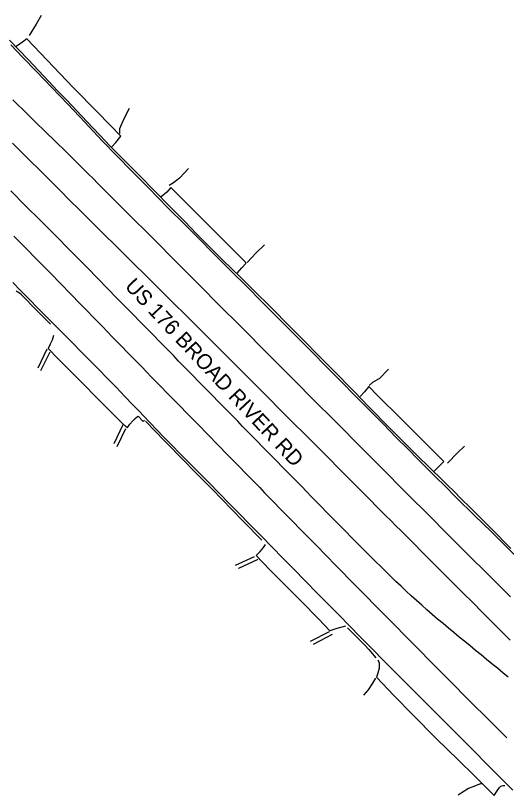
# Model space of a CAD drawing. Extents: x 1970211 to 1973046, y 801032 to 804001.
# Drawn here: x 1972080.5 to 1972255, y 802005.1 to 802282.3 of the extents above; entities that cross this region are included whole.
import ezdxf

# ---------------------------------------------------------------- set-up
doc = ezdxf.new("R2010")
doc.units = 0
for name, color, linetype in [('RD_EX_Conc', 7, 'Continuous'), ('RD_EX_Road', 7, 'Continuous'), ('RD_EX_Road_Paint', 7, 'Continuous'), ('RD_TX_RoadID', 7, 'Continuous')]:
    doc.layers.add(name, color=color, linetype=linetype)

msp = doc.modelspace()

# ---------------------------------------------------------------- linework, layer by layer
at = {"layer": 'RD_EX_Conc'}
for points in [[(1972078.39, 802273.57), (1972081.68, 802270.1), (1972084.94, 802266.67), (1972088.67, 802262.74), (1972092.37, 802258.83), (1972095.56, 802255.47), (1972098.68, 802252.21), (1972102.14, 802248.61), (1972106.01, 802244.56), (1972110.35, 802239.96), (1972114.14, 802235.95), (1972116.34, 802233.7), (1972117.89, 802232.16), (1972119.76, 802230.29), (1972121.47, 802228.58), (1972122.55, 802227.49), (1972123.82, 802226.22), (1972126.09, 802223.91), (1972128.4, 802221.55), (1972129.79, 802220.11), (1972131.3, 802218.56), (1972133.97, 802215.88), (1972137.29, 802212.53), (1972140.78, 802208.98), (1972144.77, 802204.91), (1972149.62, 802200), (1972154.24, 802195.38), (1972157.53, 802192.16), (1972160.33, 802189.46), (1972163.44, 802186.4), (1972166.67, 802183.19), (1972169.81, 802180.04), (1972172.99, 802176.84), (1972176.33, 802173.47), (1972179.87, 802169.91), (1972183.64, 802166.11), (1972187.6, 802162.13), (1972191.71, 802157.99), (1972195.51, 802154.16), (1972198.53, 802151.09), (1972201.09, 802148.46), (1972203.49, 802145.95), (1972205.89, 802143.45), (1972208.45, 802140.86), (1972211.35, 802137.93), (1972214.79, 802134.44), (1972218.3, 802130.89), (1972221.41, 802127.79), (1972224.22, 802125.03), (1972226.79, 802122.49), (1972229.05, 802120.28), (1972230.93, 802118.47), (1972232.58, 802116.88), (1972234.15, 802115.34), (1972236.14, 802113.36), (1972239.05, 802110.46), (1972242, 802107.53), (1972244.1, 802105.46), (1972246.16, 802103.42), (1972248.98, 802100.56), (1972251.92, 802097.58), (1972254.32, 802095.16), (1972256.6, 802092.88)], [(1972114.73, 802235.71), (1972116.12, 802237.25), (1972117.98, 802239.48), (1972109.75, 802247.84), (1972100.93, 802256.8), (1972091.73, 802266.51), (1972084.49, 802274.07), (1972082.97, 802272.87), (1972080.68, 802271.35)], [(1972141.95, 802228.02), (1972138.83, 802224.5), (1972136.67, 802222.89), (1972135.11, 802221.96)], [(1972159.23, 802190.81), (1972160.93, 802192.61), (1972162.42, 802194.2), (1972162.42, 802194.53), (1972155.61, 802201.28), (1972147.87, 802209.03), (1972140.09, 802216.86), (1972135.75, 802221.24), (1972134.27, 802219.51), (1972132.26, 802217.89)], [(1972169, 802200.87), (1972166.06, 802197.95), (1972162.86, 802194.59)], [(1972092.99, 802172.59), (1972086.67, 802178.96), (1972084.09, 802181.6), (1972083.14, 802182.61), (1972082.52, 802183.12), (1972081.86, 802183.63), (1972080.68, 802184.37)], [(1972093.96, 802168.57), (1972093.49, 802166.97), (1972092.85, 802165.51), (1972092.14, 802163.93), (1972095.48, 802160.4), (1972103.46, 802152.51), (1972110.42, 802145.35), (1972118.51, 802137.32), (1972119.62, 802136.35), (1972120.25, 802135.87), (1972121.16, 802137.05), (1972122.19, 802138.24), (1972123.06, 802139.1), (1972123.8, 802139.79), (1972124.08, 802139.99), (1972125.93, 802138.07), (1972126.33, 802138.56)], [(1972088.49, 802157.1), (1972091.77, 802163.92)], [(1972213.03, 802156.67), (1972209.93, 802153.31), (1972207.43, 802151.86), (1972206.19, 802150.85)], [(1972229.31, 802120.34), (1972231.21, 802122.28), (1972232.76, 802123.83), (1972225.24, 802131.24), (1972217.53, 802139.02), (1972209.19, 802147.31), (1972206.11, 802150.45), (1972204.55, 802148.54), (1972202.99, 802146.9)], [(1972116.64, 802129.19), (1972119.66, 802135.6)], [(1972126.75, 802138.15), (1972130.28, 802134.5), (1972133.23, 802131.45), (1972135.8, 802128.8), (1972138.25, 802126.29), (1972140.79, 802123.71), (1972143.58, 802120.87), (1972146.73, 802117.65), (1972150.38, 802113.96), (1972154.05, 802110.23), (1972157.27, 802106.92), (1972161.47, 802102.59), (1972168.03, 802095.8)], [(1972240.08, 802129.28), (1972237.66, 802126.85), (1972234.08, 802123.24)], [(1972197.82, 802065.23), (1972194.76, 802064.5), (1972192.24, 802063.68), (1972188.31, 802067.8), (1972181.94, 802074.32), (1972176.69, 802079.53), (1972170.9, 802085.31), (1972166.07, 802090.39), (1972167.46, 802091.79), (1972168.66, 802093.26), (1972169.35, 802094.35)], [(1972158.73, 802086.95), (1972165.44, 802090.06)], [(1972209.24, 802053.36), (1972209.75, 802052.22), (1972209.79, 802050.31), (1972209.34, 802048.54), (1972208.77, 802047.19), (1972215.03, 802040.64), (1972221.71, 802033.8), (1972230.04, 802025.31), (1972237.94, 802017.65), (1972243.51, 802012.16), (1972246.5, 802009.27), (1972250.67, 802005.14), (1972251.53, 802006.41), (1972252.49, 802007.95), (1972253.04, 802008.39), (1972253.88, 802008.62), (1972254.42, 802008.62)]]:
    msp.add_lwpolyline(points, dxfattribs=at)
at = {"layer": 'RD_EX_Road'}
for points in [[(1972089.59, 802282.31), (1972087.83, 802279.31), (1972085.34, 802275.23)], [(1972259.9, 802088.59), (1972254.78, 802093.69), (1972249.66, 802098.77), (1972243.69, 802104.66), (1972237.18, 802111.08), (1972232.7, 802115.49), (1972230.26, 802117.9), (1972227.41, 802120.76), (1972223.81, 802124.39), (1972219.91, 802128.34), (1972215.75, 802132.52), (1972211.26, 802137.08), (1972206.43, 802141.99), (1972201.4, 802147.09), (1972196.21, 802152.3), (1972191.1, 802157.47), (1972185.96, 802162.65), (1972180.15, 802168.51), (1972173.74, 802174.94), (1972167.95, 802180.73), (1972162.79, 802185.87), (1972157.15, 802191.52), (1972151.02, 802197.67), (1972145.55, 802203.16), (1972140.64, 802208.06), (1972134.69, 802214.04), (1972127.74, 802221.05), (1972121.72, 802227.14), (1972116.7, 802232.24), (1972111.23, 802237.96), (1972105.17, 802244.41), (1972099.16, 802250.75), (1972093.34, 802256.82), (1972087.93, 802262.44), (1972083.01, 802267.54), (1972078.79, 802271.9)], [(1972117.53, 802240.39), (1972117.62, 802242.22), (1972119.14, 802245.74), (1972121.02, 802249.43)], [(1972257.32, 802006.96), (1972253.8, 802010.49), (1972250.64, 802013.66), (1972247.69, 802016.64), (1972243.64, 802020.69), (1972238.54, 802025.8), (1972233.81, 802030.53), (1972229.62, 802034.74), (1972225.41, 802038.98), (1972221.05, 802043.36), (1972216.46, 802047.97), (1972211.71, 802052.78), (1972207.22, 802057.3), (1972203.05, 802061.48), (1972199.17, 802065.41), (1972195.5, 802069.15), (1972191.7, 802073.02), (1972187.72, 802077.07), (1972183.57, 802081.29), (1972179.31, 802085.61), (1972175.38, 802089.62), (1972171.74, 802093.34), (1972167.9, 802097.26), (1972163.85, 802101.38), (1972160, 802105.28), (1972156.41, 802108.93), (1972152.85, 802112.55), (1972149.3, 802116.18), (1972145.8, 802119.74), (1972142.37, 802123.2), (1972139.07, 802126.53), (1972136.05, 802129.59), (1972134.04, 802131.65), (1972132.89, 802132.85), (1972130.96, 802134.87), (1972128.21, 802137.73), (1972126.01, 802140.02), (1972124.4, 802141.71), (1972122.21, 802143.98), (1972119.33, 802146.97), (1972116.26, 802150.18), (1972113.13, 802153.47), (1972110.17, 802156.47), (1972107.36, 802159.24), (1972104.12, 802162.51), (1972100.53, 802166.22), (1972097.48, 802169.33), (1972094.96, 802171.86), (1972092.01, 802174.81), (1972088.58, 802178.25), (1972085.31, 802181.54), (1972082.31, 802184.58), (1972079.52, 802187.42)], [(1972089.46, 802156.14), (1972092.78, 802162.77)], [(1972115.6, 802130.23), (1972118.73, 802136.96)], [(1972159.8, 802085.86), (1972159.92, 802085.92), (1972166.7, 802089.12)], [(1972198.54, 802064.7), (1972202.25, 802060.95), (1972204.38, 802058.82), (1972206.13, 802056.94), (1972208.6, 802054.08)], [(1972185.3, 802059.99), (1972192.06, 802063.36)], [(1972186.38, 802058.9), (1972186.38, 802058.9), (1972193.19, 802062.39)], [(1972204.26, 802040.75), (1972205.92, 802042.7), (1972207.5, 802045), (1972208.62, 802046.78)], [(1972246.38, 802009.24), (1972245.8, 802009.21), (1972244.88, 802008.93), (1972243.99, 802008.56), (1972241.52, 802007.56), (1972239.22, 802006.17), (1972237.85, 802005.26)]]:
    msp.add_lwpolyline(points, dxfattribs=at)
at = {"layer": 'RD_EX_Road_Paint'}
for points in [[(1972256.4, 802075.73), (1972254.63, 802077.49), (1972252.86, 802079.26), (1972251.09, 802081.03), (1972249.32, 802082.79), (1972247.55, 802084.56), (1972245.78, 802086.32), (1972244.01, 802088.09), (1972242.24, 802089.85), (1972240.47, 802091.62), (1972238.7, 802093.38), (1972236.93, 802095.15), (1972235.16, 802096.92), (1972233.39, 802098.68), (1972231.63, 802100.45), (1972229.86, 802102.22), (1972228.1, 802103.99), (1972226.33, 802105.76), (1972224.57, 802107.53), (1972222.8, 802109.3), (1972221.04, 802111.08), (1972219.27, 802112.85), (1972217.51, 802114.62), (1972215.74, 802116.39), (1972213.98, 802118.16), (1972212.22, 802119.93), (1972210.45, 802121.7), (1972208.69, 802123.47), (1972206.92, 802125.24), (1972205.16, 802127.01), (1972203.39, 802128.78), (1972201.63, 802130.56), (1972199.86, 802132.33), (1972198.1, 802134.1), (1972196.33, 802135.87), (1972194.57, 802137.64), (1972192.8, 802139.41), (1972191.04, 802141.18), (1972189.27, 802142.95), (1972187.51, 802144.72), (1972185.75, 802146.49), (1972183.98, 802148.26), (1972182.22, 802150.03), (1972180.45, 802151.81), (1972178.69, 802153.58), (1972176.92, 802155.35), (1972175.16, 802157.12), (1972173.39, 802158.89), (1972171.63, 802160.66), (1972169.86, 802162.43), (1972168.1, 802164.2), (1972166.33, 802165.97), (1972164.57, 802167.74), (1972162.81, 802169.51), (1972161.04, 802171.28), (1972159.28, 802173.06), (1972157.51, 802174.83), (1972155.75, 802176.6), (1972153.98, 802178.37), (1972152.22, 802180.14), (1972150.45, 802181.91), (1972148.69, 802183.68), (1972146.92, 802185.45), (1972145.16, 802187.22), (1972143.39, 802188.99), (1972141.63, 802190.76), (1972139.86, 802192.54), (1972138.1, 802194.31), (1972136.34, 802196.08), (1972134.57, 802197.85), (1972132.81, 802199.62), (1972131.04, 802201.39), (1972129.28, 802203.16), (1972127.51, 802204.93), (1972125.75, 802206.7), (1972123.98, 802208.47), (1972122.22, 802210.24), (1972120.45, 802212.01), (1972118.69, 802213.78), (1972116.91, 802215.54), (1972115.14, 802217.31), (1972113.36, 802219.07), (1972111.59, 802220.83), (1972109.81, 802222.59), (1972108.04, 802224.35), (1972106.27, 802226.11), (1972104.49, 802227.87), (1972102.72, 802229.63), (1972100.94, 802231.39), (1972099.17, 802233.15), (1972097.39, 802234.91), (1972095.62, 802236.67), (1972093.84, 802238.43), (1972092.04, 802240.17), (1972090.25, 802241.91), (1972088.46, 802243.65), (1972086.66, 802245.39), (1972084.87, 802247.14), (1972083.08, 802248.88), (1972081.28, 802250.62), (1972079.49, 802252.36)], [(1972256.35, 802060.35), (1972254.58, 802062.11), (1972252.81, 802063.88), (1972251.04, 802065.65), (1972249.27, 802067.41), (1972247.5, 802069.18), (1972245.73, 802070.95), (1972243.96, 802072.71), (1972242.19, 802074.48), (1972240.42, 802076.24), (1972238.66, 802078.01), (1972236.89, 802079.78), (1972235.12, 802081.55), (1972233.35, 802083.32), (1972231.58, 802085.08), (1972229.82, 802086.85), (1972228.05, 802088.62), (1972226.28, 802090.39), (1972224.51, 802092.15), (1972222.75, 802093.93), (1972220.99, 802095.7), (1972219.22, 802097.47), (1972217.46, 802099.24), (1972215.7, 802101.01), (1972213.93, 802102.79), (1972212.17, 802104.56), (1972210.41, 802106.33), (1972208.64, 802108.1), (1972206.88, 802109.88), (1972205.12, 802111.65), (1972203.35, 802113.42), (1972201.59, 802115.19), (1972199.83, 802116.96), (1972198.06, 802118.74), (1972196.3, 802120.51), (1972194.54, 802122.28), (1972192.77, 802124.05), (1972191.01, 802125.82), (1972189.24, 802127.59), (1972187.47, 802129.36), (1972185.7, 802131.13), (1972183.93, 802132.89), (1972182.16, 802134.66), (1972180.39, 802136.42), (1972178.62, 802138.19), (1972176.86, 802139.96), (1972175.09, 802141.73), (1972173.33, 802143.5), (1972171.56, 802145.27), (1972169.8, 802147.04), (1972168.03, 802148.81), (1972166.27, 802150.58), (1972164.51, 802152.35), (1972162.74, 802154.13), (1972160.98, 802155.9), (1972159.21, 802157.67), (1972157.44, 802159.43), (1972155.67, 802161.2), (1972153.9, 802162.96), (1972152.13, 802164.72), (1972150.36, 802166.49), (1972148.58, 802168.25), (1972146.81, 802170.02), (1972145.04, 802171.78), (1972143.27, 802173.54), (1972141.5, 802175.31), (1972139.73, 802177.08), (1972137.96, 802178.84), (1972136.19, 802180.61), (1972134.43, 802182.38), (1972132.66, 802184.15), (1972130.89, 802185.91), (1972129.11, 802187.67), (1972127.33, 802189.43), (1972125.55, 802191.18), (1972123.78, 802192.94), (1972122, 802194.7), (1972120.22, 802196.46), (1972118.44, 802198.21), (1972116.66, 802199.97), (1972114.89, 802201.73), (1972113.11, 802203.49), (1972111.33, 802205.24), (1972109.55, 802207), (1972107.78, 802208.76), (1972106.01, 802210.52), (1972104.23, 802212.29), (1972102.46, 802214.05), (1972100.69, 802215.81), (1972098.91, 802217.57), (1972097.14, 802219.34), (1972095.37, 802221.1), (1972093.59, 802222.86), (1972091.82, 802224.62), (1972090.05, 802226.39), (1972088.27, 802228.15), (1972086.5, 802229.91), (1972084.73, 802231.67), (1972082.96, 802233.44), (1972081.18, 802235.2), (1972079.4, 802236.96)], [(1972255.67, 802047.18), (1972253.73, 802048.76), (1972251.79, 802050.33), (1972249.85, 802051.91), (1972247.91, 802053.49), (1972245.98, 802055.07), (1972244.04, 802056.66), (1972242.11, 802058.24), (1972240.18, 802059.83), (1972238.24, 802061.41), (1972236.31, 802063), (1972234.38, 802064.59), (1972232.47, 802066.2), (1972230.56, 802067.82), (1972228.65, 802069.43), (1972226.76, 802071.06), (1972224.9, 802072.73), (1972223.04, 802074.4), (1972221.18, 802076.07), (1972219.34, 802077.76), (1972217.53, 802079.49), (1972215.72, 802081.22), (1972213.92, 802082.95), (1972212.11, 802084.68), (1972210.34, 802086.44), (1972208.57, 802088.2), (1972206.8, 802089.97), (1972205.03, 802091.73), (1972203.26, 802093.5), (1972201.5, 802095.27), (1972199.74, 802097.05), (1972197.99, 802098.84), (1972196.24, 802100.62), (1972194.48, 802102.4), (1972192.73, 802104.18), (1972190.98, 802105.96), (1972189.22, 802107.75), (1972187.47, 802109.53), (1972185.72, 802111.31), (1972183.97, 802113.1), (1972182.22, 802114.88), (1972180.47, 802116.67), (1972178.72, 802118.46), (1972176.97, 802120.24), (1972175.22, 802122.03), (1972173.47, 802123.81), (1972171.72, 802125.6), (1972169.98, 802127.39), (1972168.23, 802129.17), (1972166.48, 802130.96), (1972164.73, 802132.74), (1972162.97, 802134.53), (1972161.22, 802136.31), (1972159.47, 802138.1), (1972157.72, 802139.88), (1972155.97, 802141.66), (1972154.22, 802143.45), (1972152.47, 802145.23), (1972150.72, 802147.02), (1972148.97, 802148.8), (1972147.22, 802150.59), (1972145.47, 802152.38), (1972143.73, 802154.17), (1972141.98, 802155.96), (1972140.23, 802157.75), (1972138.49, 802159.53), (1972136.74, 802161.32), (1972134.99, 802163.11), (1972133.25, 802164.9), (1972131.5, 802166.68), (1972129.74, 802168.47), (1972127.99, 802170.25), (1972126.24, 802172.04), (1972124.49, 802173.82), (1972122.74, 802175.61), (1972120.99, 802177.39), (1972119.24, 802179.17), (1972117.49, 802180.96), (1972115.74, 802182.74), (1972113.99, 802184.53), (1972112.24, 802186.31), (1972110.49, 802188.1), (1972108.74, 802189.88), (1972106.99, 802191.67), (1972105.23, 802193.45), (1972103.48, 802195.23), (1972101.72, 802197.01), (1972099.96, 802198.78), (1972098.2, 802200.56), (1972096.44, 802202.34), (1972094.68, 802204.11), (1972092.92, 802205.89), (1972091.16, 802207.67), (1972089.4, 802209.43), (1972087.63, 802211.2), (1972085.86, 802212.97), (1972084.09, 802214.73), (1972082.32, 802216.5), (1972080.55, 802218.27), (1972078.78, 802220.03)], [(1972079.91, 802203.91), (1972081.67, 802202.13), (1972083.43, 802200.35), (1972085.18, 802198.57), (1972086.94, 802196.79), (1972088.69, 802195.01), (1972090.45, 802193.23), (1972092.21, 802191.45), (1972093.96, 802189.67), (1972095.71, 802187.88), (1972097.45, 802186.09), (1972099.19, 802184.3), (1972100.94, 802182.51), (1972102.68, 802180.72), (1972104.42, 802178.92), (1972106.16, 802177.13), (1972107.91, 802175.34), (1972109.65, 802173.55), (1972111.39, 802171.75), (1972113.14, 802169.96), (1972114.88, 802168.17), (1972116.62, 802166.38), (1972118.36, 802164.59), (1972120.11, 802162.79), (1972121.85, 802161), (1972123.6, 802159.21), (1972125.35, 802157.43), (1972127.1, 802155.64), (1972128.85, 802153.85), (1972130.59, 802152.07), (1972132.34, 802150.28), (1972134.09, 802148.5), (1972135.84, 802146.71), (1972137.59, 802144.92), (1972139.34, 802143.14), (1972141.09, 802141.35), (1972142.84, 802139.57), (1972144.59, 802137.78), (1972146.34, 802135.99), (1972148.09, 802134.21), (1972149.84, 802132.42), (1972151.58, 802130.63), (1972153.33, 802128.84), (1972155.07, 802127.05), (1972156.82, 802125.26), (1972158.56, 802123.47), (1972160.31, 802121.68), (1972162.05, 802119.89), (1972163.8, 802118.1), (1972165.54, 802116.31), (1972167.29, 802114.52), (1972169.03, 802112.73), (1972170.77, 802110.94), (1972172.52, 802109.15), (1972174.26, 802107.36), (1972176.01, 802105.57), (1972177.75, 802103.77), (1972179.5, 802101.99), (1972181.26, 802100.21), (1972183.01, 802098.43), (1972184.76, 802096.64), (1972186.52, 802094.86), (1972188.27, 802093.08), (1972190.03, 802091.3), (1972191.78, 802089.52), (1972193.53, 802087.74), (1972195.29, 802085.96), (1972197.04, 802084.17), (1972198.8, 802082.39), (1972200.55, 802080.61), (1972202.3, 802078.83), (1972204.06, 802077.05), (1972205.81, 802075.27), (1972207.57, 802073.49), (1972209.32, 802071.71), (1972211.08, 802069.93), (1972212.84, 802068.15), (1972214.59, 802066.37), (1972216.35, 802064.59), (1972218.11, 802062.82), (1972219.86, 802061.04), (1972221.62, 802059.26), (1972223.38, 802057.48), (1972225.14, 802055.7), (1972226.89, 802053.92), (1972228.65, 802052.14), (1972230.41, 802050.37), (1972232.16, 802048.59), (1972233.92, 802046.81), (1972235.68, 802045.03), (1972237.44, 802043.26), (1972239.21, 802041.49), (1972240.98, 802039.73), (1972242.75, 802037.96), (1972244.52, 802036.19), (1972246.29, 802034.43), (1972248.05, 802032.66), (1972249.82, 802030.89), (1972251.59, 802029.12), (1972253.36, 802027.36), (1972255.13, 802025.59)]]:
    msp.add_lwpolyline(points, dxfattribs=at)

# ---------------------------------------------------------------- texts
at = {"layer": 'RD_TX_RoadID'}
msp.add_text('US 176 BROAD RIVER RD', height=5.4, rotation=313.1694, dxfattribs=at).set_placement((1972119.06, 802185.87))

doc.saveas('drawing.dxf')
